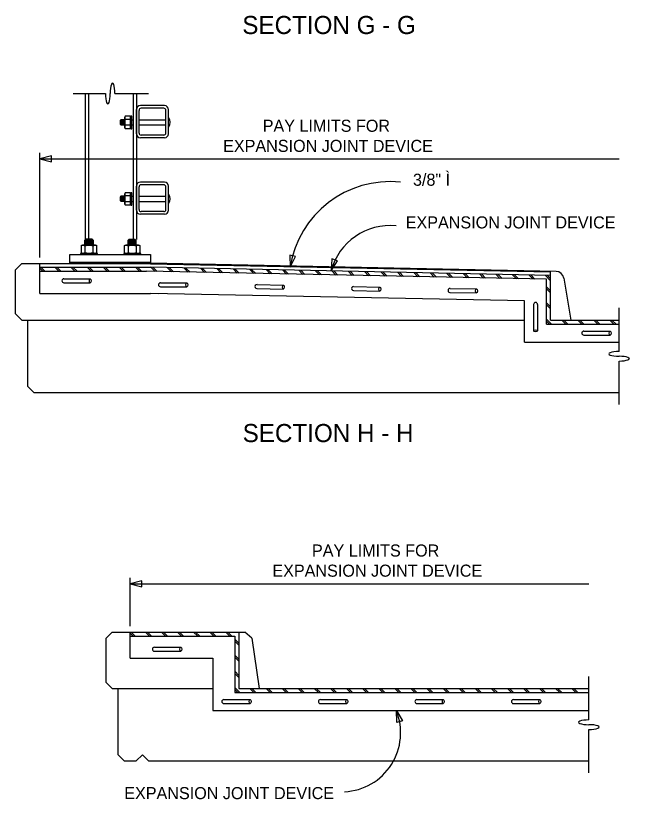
# Model space of a CAD drawing. Extents: x 19590 to 20151, y 19944 to 20103.
# Drawn here: x 19848.01 to 19871.53, y 20034.28 to 20064.29 of the extents above; entities that cross this region are included whole.
import ezdxf

# ---------------------------------------------------------------- set-up
doc = ezdxf.new("R2010")
doc.units = 0
for name, color, linetype in [('DETAIL_PR', 7, 'Continuous'), ('DETAIL_TEXT_DIMEN_PR', 7, 'Continuous'), ('Level 1', 7, 'Continuous'), ('Sheet_Label_Str_Wt0', 7, 'Continuous')]:
    doc.layers.add(name, color=color, linetype=linetype)

msp = doc.modelspace()

# ---------------------------------------------------------------- linework, layer by layer
at = {"layer": 'DETAIL_PR'}
for p, q in [((19850.208, 20061.308), (19851.451, 20061.308)), ((19850.671, 20061.308), (19850.671, 20055.727)), ((19850.798, 20061.308), (19850.798, 20055.727)), ((19851.815, 20061.308), (19853.099, 20061.308)), ((19852.509, 20061.308), (19852.509, 20055.725)), ((19852.636, 20061.308), (19852.636, 20055.725)), ((19852.636, 20059.766), (19852.636, 20060.691)), ((19852.739, 20059.792), (19852.739, 20060.665)), ((19853.715, 20060.845), (19852.79, 20060.845)), ((19853.689, 20060.742), (19852.816, 20060.742)), ((19853.766, 20059.792), (19853.766, 20060.665)), ((19853.868, 20059.766), (19853.868, 20060.691)), ((19852.044, 20060.304), (19852.044, 20060.11)), ((19852.085, 20060.304), (19852.085, 20060.11)), ((19852.111, 20060.304), (19852.111, 20060.11)), ((19852.152, 20060.304), (19852.152, 20060.11)), ((19852.395, 20060.319), (19852.206, 20060.319)), ((19852.462, 20060.304), (19852.489, 20060.304)), ((19852.739, 20060.303), (19853.766, 20060.303)), ((19852.071, 20060.266), (19852.071, 20060.147)), ((19852.099, 20060.266), (19852.099, 20060.147)), ((19852.132, 20060.266), (19852.132, 20060.147)), ((19852.165, 20060.266), (19852.165, 20060.147)), ((19852.395, 20060.094), (19852.206, 20060.094)), ((19852.462, 20060.109), (19852.489, 20060.109)), ((19852.739, 20060.109), (19853.766, 20060.109)), ((19853.689, 20059.715), (19852.816, 20059.715)), ((19853.715, 20059.613), (19852.79, 20059.613)), ((19853.715, 20057.916), (19852.79, 20057.916)), ((19852.636, 20056.837), (19852.636, 20057.762)), ((19852.739, 20056.863), (19852.739, 20057.736)), ((19853.689, 20057.813), (19852.816, 20057.813)), ((19853.766, 20056.863), (19853.766, 20057.736)), ((19853.868, 20056.837), (19853.868, 20057.762)), ((19852.044, 20057.375), (19852.044, 20057.181)), ((19852.071, 20057.336), (19852.071, 20057.218)), ((19852.085, 20057.375), (19852.085, 20057.181)), ((19852.099, 20057.336), (19852.099, 20057.218)), ((19852.111, 20057.375), (19852.111, 20057.181)), ((19852.132, 20057.336), (19852.132, 20057.218)), ((19852.152, 20057.375), (19852.152, 20057.181)), ((19852.165, 20057.336), (19852.165, 20057.218)), ((19852.395, 20057.39), (19852.206, 20057.39)), ((19852.462, 20057.375), (19852.489, 20057.375)), ((19852.739, 20057.374), (19853.766, 20057.374)), ((19852.395, 20057.164), (19852.206, 20057.164)), ((19852.462, 20057.18), (19852.489, 20057.18)), ((19852.739, 20057.18), (19853.766, 20057.18)), ((19853.715, 20056.683), (19852.79, 20056.683)), ((19853.689, 20056.786), (19852.816, 20056.786)), ((19850.988, 20055.687), (19850.652, 20055.687)), ((19850.988, 20055.648), (19850.652, 20055.648)), ((19850.988, 20055.607), (19850.652, 20055.607)), ((19850.988, 20055.568), (19850.652, 20055.568)), ((19850.988, 20055.528), (19850.652, 20055.528)), ((19850.665, 20055.475), (19850.665, 20055.223)), ((19850.974, 20055.475), (19850.974, 20055.223)), ((19852.635, 20055.685), (19852.312, 20055.685)), ((19852.635, 20055.646), (19852.312, 20055.646)), ((19852.635, 20055.605), (19852.312, 20055.605)), ((19852.635, 20055.565), (19852.312, 20055.565)), ((19852.635, 20055.526), (19852.312, 20055.526)), ((19852.326, 20055.472), (19852.326, 20055.22)), ((19852.635, 20055.472), (19852.635, 20055.22)), ((19848.241, 20054.794), (19848.01, 20054.563)), ((19848.241, 20054.794), (19853.175, 20054.794)), ((19848.935, 20053.652), (19848.935, 20054.794)), ((19848.935, 20054.657), (19853.175, 20054.657)), ((19849.051, 20054.503), (19848.935, 20054.618)), ((19849.128, 20054.503), (19848.974, 20054.657)), ((19849.667, 20054.503), (19849.513, 20054.657)), ((19849.744, 20054.503), (19849.59, 20054.657)), ((19850.284, 20054.503), (19850.13, 20054.657)), ((19850.361, 20054.503), (19850.207, 20054.657)), ((19850.901, 20054.503), (19850.747, 20054.657)), ((19850.978, 20054.503), (19850.824, 20054.657)), ((19851.517, 20054.503), (19851.363, 20054.657)), ((19851.594, 20054.503), (19851.44, 20054.657)), ((19852.134, 20054.503), (19851.98, 20054.657)), ((19852.211, 20054.503), (19852.057, 20054.657)), ((19852.751, 20054.503), (19852.597, 20054.657)), ((19852.828, 20054.503), (19852.674, 20054.657)), ((19868.721, 20054.497), (19853.175, 20054.808)), ((19868.514, 20054.463), (19853.175, 20054.77)), ((19868.514, 20054.347), (19853.175, 20054.654)), ((19853.357, 20054.496), (19853.2, 20054.653)), ((19853.436, 20054.494), (19853.278, 20054.652)), ((19853.984, 20054.486), (19853.83, 20054.64)), ((19854.065, 20054.482), (19853.908, 20054.639)), ((19854.616, 20054.471), (19854.458, 20054.628)), ((19854.694, 20054.469), (19854.537, 20054.627)), ((19855.245, 20054.458), (19855.088, 20054.616)), ((19855.324, 20054.457), (19855.166, 20054.614)), ((19855.874, 20054.446), (19855.717, 20054.603)), ((19855.953, 20054.444), (19855.795, 20054.601)), ((19856.503, 20054.433), (19856.346, 20054.59)), ((19856.582, 20054.432), (19856.425, 20054.589)), ((19857.133, 20054.421), (19856.975, 20054.578)), ((19857.211, 20054.419), (19857.054, 20054.576)), ((19848.01, 20052.867), (19848.01, 20054.563)), ((19848.935, 20054.503), (19853.021, 20054.503)), ((19868.36, 20054.196), (19853.021, 20054.503)), ((19857.762, 20054.408), (19857.605, 20054.565)), ((19857.841, 20054.406), (19857.683, 20054.564)), ((19858.391, 20054.395), (19858.234, 20054.553)), ((19858.47, 20054.394), (19858.312, 20054.551)), ((19859.02, 20054.383), (19858.863, 20054.54)), ((19859.099, 20054.381), (19858.942, 20054.539)), ((19859.65, 20054.37), (19859.492, 20054.528)), ((19859.728, 20054.369), (19859.571, 20054.526)), ((19860.279, 20054.358), (19860.122, 20054.515)), ((19860.358, 20054.356), (19860.2, 20054.513)), ((19860.908, 20054.345), (19860.751, 20054.502)), ((19860.987, 20054.343), (19860.829, 20054.501)), ((19861.537, 20054.332), (19861.38, 20054.49)), ((19861.616, 20054.331), (19861.459, 20054.488)), ((19862.167, 20054.32), (19862.009, 20054.477)), ((19862.245, 20054.318), (19862.088, 20054.476)), ((19862.796, 20054.307), (19862.639, 20054.465)), ((19862.875, 20054.306), (19862.717, 20054.463)), ((19863.425, 20054.295), (19863.268, 20054.452)), ((19863.504, 20054.293), (19863.346, 20054.45)), ((19864.054, 20054.282), (19863.897, 20054.439)), ((19864.133, 20054.281), (19863.976, 20054.438)), ((19864.684, 20054.27), (19864.526, 20054.427)), ((19864.762, 20054.268), (19864.605, 20054.425)), ((19865.313, 20054.257), (19865.156, 20054.414)), ((19865.392, 20054.255), (19865.234, 20054.413)), ((19865.942, 20054.244), (19865.785, 20054.402)), ((19866.021, 20054.243), (19865.863, 20054.4)), ((19866.571, 20054.232), (19866.414, 20054.389)), ((19866.65, 20054.23), (19866.493, 20054.388)), ((19867.201, 20054.219), (19867.043, 20054.377)), ((19867.281, 20054.216), (19867.122, 20054.375)), ((19867.83, 20054.207), (19867.673, 20054.364)), ((19867.909, 20054.205), (19867.751, 20054.362)), ((19868.514, 20054.139), (19868.302, 20054.351)), ((19868.514, 20054.216), (19868.38, 20054.35)), ((19868.514, 20052.636), (19868.514, 20054.501)), ((19849.86, 20054.216), (19850.871, 20054.216)), ((19849.86, 20054.062), (19850.871, 20054.062)), ((19853.56, 20054.062), (19854.571, 20054.062)), ((19857.261, 20053.994), (19858.272, 20053.974)), ((19868.36, 20052.482), (19868.36, 20054.196)), ((19869.019, 20054.239), (19869.285, 20052.636)), ((19853.56, 20053.908), (19854.571, 20053.908)), ((19857.258, 20053.84), (19858.269, 20053.819)), ((19860.957, 20053.766), (19861.968, 20053.745)), ((19860.96, 20053.92), (19861.971, 20053.9)), ((19864.656, 20053.692), (19865.668, 20053.671)), ((19864.659, 20053.846), (19865.671, 20053.825)), ((19868.514, 20053.754), (19868.36, 20053.908)), ((19868.514, 20053.676), (19868.36, 20053.831)), ((19848.935, 20053.652), (19853.175, 20053.652)), ((19867.512, 20053.365), (19853.175, 20053.652)), ((19853.483, 20053.645), (19853.175, 20053.652)), ((19867.512, 20051.788), (19867.512, 20053.365)), ((19867.859, 20053.232), (19867.859, 20052.219)), ((19867.859, 20053.232), (19867.859, 20052.373)), ((19868.013, 20053.232), (19868.013, 20052.219)), ((19868.013, 20053.232), (19868.013, 20052.373)), ((19868.514, 20053.137), (19868.36, 20053.291)), ((19868.514, 20053.06), (19868.36, 20053.214)), ((19871.135, 20051.43), (19871.135, 20053.098)), ((19848.241, 20052.636), (19848.01, 20052.867)), ((19848.241, 20052.636), (19867.512, 20052.636)), ((19848.473, 20050.092), (19848.473, 20052.636)), ((19868.553, 20052.482), (19868.36, 20052.674)), ((19868.476, 20052.482), (19868.36, 20052.597)), ((19868.36, 20052.482), (19871.135, 20052.482)), ((19868.514, 20052.636), (19871.135, 20052.636)), ((19869.092, 20052.482), (19868.938, 20052.636)), ((19869.169, 20052.482), (19869.015, 20052.636)), ((19869.709, 20052.482), (19869.555, 20052.636)), ((19869.786, 20052.482), (19869.632, 20052.636)), ((19870.326, 20052.482), (19870.172, 20052.636)), ((19870.403, 20052.482), (19870.249, 20052.636)), ((19870.942, 20052.482), (19870.788, 20052.636)), ((19871.019, 20052.482), (19870.865, 20052.636)), ((19869.786, 20052.212), (19870.798, 20052.212)), ((19869.786, 20052.057), (19870.798, 20052.057)), ((19867.512, 20051.788), (19871.135, 20051.788)), ((19871.135, 20049.398), (19871.135, 20051.066)), ((19848.473, 20050.092), (19848.704, 20049.861)), ((19848.704, 20049.861), (19871.135, 20049.861)), ((19851.71, 20040.687), (19851.478, 20040.455)), ((19851.71, 20040.687), (19852.403, 20040.687)), ((19852.403, 20040.687), (19856.566, 20040.687)), ((19852.403, 20039.684), (19852.403, 20040.687)), ((19852.519, 20040.532), (19852.403, 20040.648)), ((19852.403, 20040.532), (19856.412, 20040.532)), ((19852.596, 20040.532), (19852.442, 20040.687)), ((19853.136, 20040.532), (19852.981, 20040.687)), ((19853.213, 20040.532), (19853.058, 20040.687)), ((19853.752, 20040.532), (19853.598, 20040.687)), ((19853.829, 20040.532), (19853.675, 20040.687)), ((19854.369, 20040.532), (19854.215, 20040.687)), ((19854.446, 20040.532), (19854.292, 20040.687)), ((19854.986, 20040.532), (19854.831, 20040.687)), ((19855.063, 20040.532), (19854.908, 20040.687)), ((19855.602, 20040.532), (19855.448, 20040.687)), ((19855.679, 20040.532), (19855.525, 20040.687)), ((19856.219, 20040.532), (19856.065, 20040.687)), ((19856.296, 20040.532), (19856.142, 20040.687)), ((19856.412, 20040.532), (19856.412, 20038.374)), ((19856.566, 20040.687), (19856.566, 20038.528)), ((19856.566, 20040.687), (19856.797, 20040.687)), ((19857.061, 20040.458), (19856.797, 20040.687)), ((19851.478, 20038.759), (19851.478, 20040.455)), ((19856.566, 20040.263), (19856.412, 20040.417)), ((19856.566, 20040.186), (19856.412, 20040.34)), ((19857.061, 20040.458), (19857.337, 20038.528)), ((19853.328, 20040.109), (19854.34, 20040.109)), ((19853.328, 20039.955), (19854.34, 20039.955)), ((19852.403, 20039.685), (19855.564, 20039.685)), ((19855.564, 20039.685), (19855.564, 20037.68)), ((19856.566, 20039.646), (19856.412, 20039.8)), ((19856.566, 20039.569), (19856.412, 20039.723)), ((19856.566, 20039.029), (19856.412, 20039.184)), ((19856.566, 20038.952), (19856.412, 20039.106)), ((19869.978, 20037.323), (19869.978, 20038.991)), ((19851.71, 20038.528), (19851.478, 20038.76)), ((19851.71, 20038.528), (19855.564, 20038.528)), ((19851.941, 20035.984), (19851.941, 20038.528)), ((19856.604, 20038.374), (19856.412, 20038.567)), ((19856.527, 20038.374), (19856.412, 20038.49)), ((19856.412, 20038.374), (19869.978, 20038.374)), ((19856.566, 20038.528), (19869.978, 20038.528)), ((19857.144, 20038.374), (19856.99, 20038.528)), ((19857.221, 20038.374), (19857.067, 20038.528)), ((19857.761, 20038.374), (19857.606, 20038.528)), ((19857.838, 20038.374), (19857.683, 20038.528)), ((19858.377, 20038.374), (19858.223, 20038.528)), ((19858.454, 20038.374), (19858.3, 20038.528)), ((19858.994, 20038.374), (19858.84, 20038.528)), ((19859.071, 20038.374), (19858.917, 20038.528)), ((19859.611, 20038.374), (19859.456, 20038.528)), ((19859.688, 20038.374), (19859.533, 20038.528)), ((19860.227, 20038.374), (19860.073, 20038.528)), ((19860.304, 20038.374), (19860.15, 20038.528)), ((19860.844, 20038.374), (19860.69, 20038.528)), ((19860.921, 20038.374), (19860.767, 20038.528)), ((19861.461, 20038.374), (19861.306, 20038.528)), ((19861.538, 20038.374), (19861.383, 20038.528)), ((19862.077, 20038.374), (19861.923, 20038.528)), ((19862.154, 20038.374), (19862, 20038.528)), ((19862.694, 20038.374), (19862.54, 20038.528)), ((19862.771, 20038.374), (19862.617, 20038.528)), ((19863.311, 20038.374), (19863.156, 20038.528)), ((19863.388, 20038.374), (19863.233, 20038.528)), ((19863.927, 20038.374), (19863.773, 20038.528)), ((19864.004, 20038.374), (19863.85, 20038.528)), ((19864.544, 20038.374), (19864.39, 20038.528)), ((19864.621, 20038.374), (19864.467, 20038.528)), ((19865.161, 20038.374), (19865.006, 20038.528)), ((19865.238, 20038.374), (19865.083, 20038.528)), ((19865.777, 20038.374), (19865.623, 20038.528)), ((19865.854, 20038.374), (19865.7, 20038.528)), ((19866.394, 20038.374), (19866.24, 20038.528)), ((19866.471, 20038.374), (19866.317, 20038.528)), ((19867.011, 20038.374), (19866.856, 20038.528)), ((19867.088, 20038.374), (19866.933, 20038.528)), ((19867.627, 20038.374), (19867.473, 20038.528)), ((19867.704, 20038.374), (19867.55, 20038.528)), ((19868.244, 20038.374), (19868.09, 20038.528)), ((19868.321, 20038.374), (19868.167, 20038.528)), ((19868.861, 20038.374), (19868.706, 20038.528)), ((19868.938, 20038.374), (19868.783, 20038.528)), ((19869.477, 20038.374), (19869.323, 20038.528)), ((19869.554, 20038.374), (19869.4, 20038.528)), ((19855.988, 20038.105), (19857, 20038.105)), ((19859.688, 20038.105), (19860.7, 20038.105)), ((19863.388, 20038.105), (19864.4, 20038.105)), ((19867.088, 20038.105), (19868.1, 20038.105)), ((19855.988, 20037.95), (19857, 20037.95)), ((19859.688, 20037.95), (19860.7, 20037.95)), ((19863.388, 20037.95), (19864.4, 20037.95)), ((19867.088, 20037.95), (19868.1, 20037.95)), ((19855.564, 20037.68), (19869.978, 20037.68)), ((19869.978, 20035.291), (19869.978, 20036.959)), ((19851.941, 20035.985), (19852.172, 20035.753)), ((19852.866, 20035.985), (19852.635, 20035.753)), ((19852.866, 20035.985), (19853.097, 20035.753)), ((19852.172, 20035.753), (19852.635, 20035.753)), ((19853.097, 20035.753), (19869.978, 20035.753))]:
    msp.add_line(p, q, dxfattribs=at)
for points in [[(19852.179, 20060.304), (19852.044, 20060.304), (19852.017, 20060.273), (19852.017, 20060.14), (19852.044, 20060.11), (19852.179, 20060.11)], [(19852.206, 20060.439), (19852.179, 20060.386), (19852.179, 20060.013), (19852.206, 20059.974), (19852.395, 20059.974), (19852.421, 20060.013), (19852.421, 20060.386), (19852.395, 20060.439), (19852.206, 20060.439)], [(19852.421, 20060.439), (19852.421, 20059.96), (19852.462, 20059.96), (19852.462, 20060.439), (19852.421, 20060.439)], [(19852.179, 20057.375), (19852.044, 20057.375), (19852.017, 20057.344), (19852.017, 20057.211), (19852.044, 20057.181), (19852.179, 20057.181)], [(19852.206, 20057.51), (19852.179, 20057.457), (19852.179, 20057.084), (19852.206, 20057.045), (19852.395, 20057.045), (19852.421, 20057.084), (19852.421, 20057.457), (19852.395, 20057.51), (19852.206, 20057.51)], [(19852.421, 20057.51), (19852.421, 20057.031), (19852.462, 20057.031), (19852.462, 20057.51), (19852.421, 20057.51)], [(19850.571, 20055.183), (19851.068, 20055.183), (19851.123, 20055.223), (19851.123, 20055.475), (19851.068, 20055.501), (19850.571, 20055.501), (19850.517, 20055.475), (19850.517, 20055.223), (19850.571, 20055.183)], [(19850.988, 20055.501), (19850.988, 20055.687), (19850.948, 20055.727), (19850.691, 20055.727), (19850.652, 20055.687), (19850.652, 20055.501)], [(19852.231, 20055.18), (19852.716, 20055.18), (19852.784, 20055.22), (19852.784, 20055.472), (19852.716, 20055.499), (19852.231, 20055.499), (19852.164, 20055.472), (19852.164, 20055.22), (19852.231, 20055.18)], [(19852.635, 20055.499), (19852.635, 20055.685), (19852.595, 20055.725), (19852.353, 20055.725), (19852.312, 20055.685), (19852.312, 20055.499)], [(19851.149, 20055.183), (19850.49, 20055.183), (19850.49, 20055.143), (19851.149, 20055.143), (19851.149, 20055.183)], [(19852.81, 20055.18), (19852.151, 20055.18), (19852.151, 20055.141), (19852.81, 20055.141), (19852.81, 20055.18)]]:
    msp.add_lwpolyline(points, dxfattribs=at)
for points in [[(19853.175, 20054.833), (19850.091, 20054.833), (19850.091, 20055.141), (19853.175, 20055.141)], [(19850.091, 20054.833), (19853.175, 20054.833), (19853.175, 20054.794), (19850.091, 20054.794)]]:
    msp.add_lwpolyline(points, close=True, dxfattribs=at)
for centre, radius, start, end in [((19852.79, 20060.691), 0.154, 90, 180), ((19852.816, 20060.665), 0.077, 90, 180), ((19853.689, 20060.665), 0.077, 0, 90), ((19853.714, 20060.691), 0.154, 0, 90), ((19853.661, 20060.206), 0.275, 319.1029, 40.8971), ((19852.79, 20059.767), 0.154, 180, 270), ((19852.816, 20059.792), 0.077, 180, 270), ((19853.689, 20059.792), 0.077, 270, 360), ((19853.714, 20059.767), 0.154, 270, 360), ((19852.79, 20057.762), 0.154, 90, 180), ((19853.714, 20057.762), 0.154, 0, 90), ((19852.816, 20057.736), 0.077, 90, 180), ((19853.689, 20057.736), 0.077, 0, 90), ((19853.661, 20057.277), 0.275, 319.1029, 40.8971), ((19852.79, 20056.838), 0.154, 180, 270), ((19852.816, 20056.863), 0.077, 180, 270), ((19853.689, 20056.863), 0.077, 270, 360), ((19853.714, 20056.838), 0.154, 270, 360), ((19868.715, 20054.189), 0.308, 9.4315, 88.8542), ((19849.86, 20054.139), 0.0771, 90, 270), ((19853.56, 20053.985), 0.0771, 90, 270), ((19857.259, 20053.917), 0.0771, 88.8543, 268.8543), ((19860.959, 20053.843), 0.0771, 88.8543, 268.8543), ((19864.658, 20053.769), 0.0771, 88.8543, 268.8543), ((19867.936, 20053.232), 0.0771, 0, 180), ((19869.786, 20052.135), 0.0771, 90, 270), ((19853.328, 20040.031), 0.0771, 90, 270), ((19855.988, 20038.027), 0.0771, 90, 270), ((19859.688, 20038.027), 0.0771, 90, 270), ((19863.388, 20038.027), 0.0771, 90, 270), ((19867.088, 20038.027), 0.0771, 90, 270)]:
    msp.add_arc(centre, radius, start, end, dxfattribs=at)
for centre, major_axis, ratio, start_param, end_param in [((19851.724, 20061.308), (0, -0.395), 0.230204, 1.570796, 4.712389), ((19851.542, 20061.308), (0, -0.395), 0.230206, 4.712389, 7.853982), ((19852.296, 20060.38), (0.105, 0), 0.985841, 2.541474, 3.741711), ((19852.583, 20060.205), (0.392, 0), 0.985841, 2.834625, 3.44856), ((19852.309, 20060.38), (0.105, 0), 0.985841, 5.683067, 6.883304), ((19852.022, 20060.205), (0.392, 0), 0.985841, 5.976218, 6.590153), ((19852.296, 20060.03), (0.105, 0), 0.985841, 2.541474, 3.741711), ((19852.309, 20060.03), (0.105, 0), 0.985841, 5.683067, 6.883304), ((19852.296, 20057.451), (0.105, 0), 0.985841, 2.541474, 3.741711), ((19852.583, 20057.276), (0.392, 0), 0.985841, 2.834625, 3.44856), ((19852.309, 20057.451), (0.105, 0), 0.985841, 5.683067, 6.883304), ((19852.022, 20057.276), (0.392, 0), 0.985841, 5.976218, 6.590153), ((19852.296, 20057.101), (0.105, 0), 0.985841, 2.541474, 3.741711), ((19852.309, 20057.101), (0.105, 0), 0.985841, 5.683067, 6.883304), ((19850.59, 20055.359), (0.136, 0), 0.985841, 0.970676, 2.170917), ((19850.821, 20054.991), (0.51, 0), 0.985841, 1.263828, 1.877765), ((19851.052, 20055.359), (0.136, 0), 0.985841, 0.970677, 2.170916), ((19852.245, 20055.357), (0.136, 0), 0.985841, 0.970676, 2.170917), ((19852.476, 20054.988), (0.51, 0), 0.985841, 1.263828, 1.877765), ((19852.708, 20055.357), (0.136, 0), 0.985841, 0.970677, 2.170916), ((19850.59, 20055.333), (0.136, 0), 0.985841, 4.112273, 5.312505), ((19850.821, 20055.701), (0.51, 0), 0.985841, 4.405422, 5.019356), ((19851.052, 20055.333), (0.136, 0), 0.985841, 4.112272, 5.312505), ((19852.245, 20055.33), (0.136, 0), 0.985841, 4.112273, 5.312505), ((19852.476, 20055.698), (0.51, 0), 0.985841, 4.405422, 5.019356), ((19852.708, 20055.33), (0.136, 0), 0.985841, 4.112272, 5.312505), ((19871.135, 20051.339), (0.395, 0), 0.230204, 1.570796, 4.712389), ((19871.135, 20051.157), (0.395, 0), 0.230206, 4.712389, 7.853982), ((19869.978, 20037.232), (0.395, 0), 0.230204, 1.570796, 4.712389), ((19869.978, 20037.05), (0.395, 0), 0.230206, 4.712389, 7.853982)]:
    msp.add_ellipse(centre, major_axis=major_axis, ratio=ratio, start_param=start_param, end_param=end_param, dxfattribs=at)
for centre, major_axis in [((19850.871, 20054.139), (0, 0.0773)), ((19854.571, 20053.985), (0, 0.0773)), ((19858.27, 20053.896), (0.0015, 0.0773)), ((19861.97, 20053.822), (0.0015, 0.0773)), ((19865.669, 20053.748), (0.0015, 0.0773)), ((19867.936, 20052.219), (0.0773, 0)), ((19870.798, 20052.134), (0, 0.0773)), ((19854.34, 20040.031), (0, 0.0773)), ((19857, 20038.027), (0, 0.0773)), ((19860.7, 20038.027), (0, 0.0773)), ((19864.4, 20038.027), (0, 0.0773)), ((19868.1, 20038.027), (0, 0.0773))]:
    msp.add_ellipse(centre, major_axis=major_axis, ratio=0.466726, dxfattribs=at)
at = {"layer": 'DETAIL_TEXT_DIMEN_PR'}
for p, q in [((19848.935, 20055.025), (19848.935, 20059.034)), ((19848.935, 20058.803), (19871.135, 20058.803)), ((19852.403, 20040.918), (19852.403, 20042.768)), ((19852.403, 20042.537), (19869.978, 20042.537))]:
    msp.add_line(p, q, dxfattribs=at)
for centre, radius, start, end in [((19862.361, 20054.058), 3.879, 84.1624, 171.0299), ((19862.361, 20053.904), 2.347, 84.1624, 164.8834), ((19860.504, 20036.831), 2.261, 272.7697, 22.0583)]:
    msp.add_arc(centre, radius, start, end, dxfattribs=at)
at = {"layer": 'Level 1'}
for p, q in [((19849.383, 20058.918), (19848.935, 20058.802)), ((19848.935, 20058.802), (19849.383, 20058.687)), ((19849.383, 20058.687), (19849.383, 20058.918)), ((19858.741, 20055.074), (19858.515, 20055.124)), ((19858.515, 20055.124), (19858.53, 20054.662)), ((19858.53, 20054.662), (19858.741, 20055.074)), ((19860.13, 20054.976), (19860.096, 20054.515)), ((19860.096, 20054.515), (19860.349, 20054.902)), ((19860.349, 20054.902), (19860.13, 20054.976)), ((19852.851, 20042.652), (19852.403, 20042.537)), ((19852.851, 20042.421), (19852.851, 20042.652)), ((19852.403, 20042.537), (19852.851, 20042.421)), ((19862.6, 20037.68), (19862.838, 20037.284)), ((19862.617, 20037.218), (19862.6, 20037.68)), ((19862.838, 20037.284), (19862.617, 20037.218))]:
    msp.add_line(p, q, dxfattribs=at)

# ---------------------------------------------------------------- texts
at = {"layer": 'DETAIL_TEXT_DIMEN_PR'}
for s, height, p in [('SECTION G - G', 0.69385, (19856.696, 20063.586)), ('PAY LIMITS FOR', 0.4625, (19857.478, 20059.843)), ('EXPANSION JOINT DEVICE', 0.4625, (19855.961, 20059.073)), ('EXPANSION JOINT DEVICE', 0.4625, (19862.959, 20056.143)), ('SECTION H - H', 0.69385, (19856.71, 20047.961)), ('PAY LIMITS FOR', 0.4625, (19859.366, 20043.578)), ('EXPANSION JOINT DEVICE', 0.4625, (19857.849, 20042.807)), ('EXPANSION JOINT DEVICE', 0.4625, (19852.172, 20034.289))]:
    msp.add_text(s, height=height, dxfattribs=at).set_placement(p)
at = {"layer": 'Sheet_Label_Str_Wt0'}
msp.add_text('3/8" Ì', height=0.4625, dxfattribs=at).set_placement((19863.238, 20057.777))

doc.saveas('drawing.dxf')
